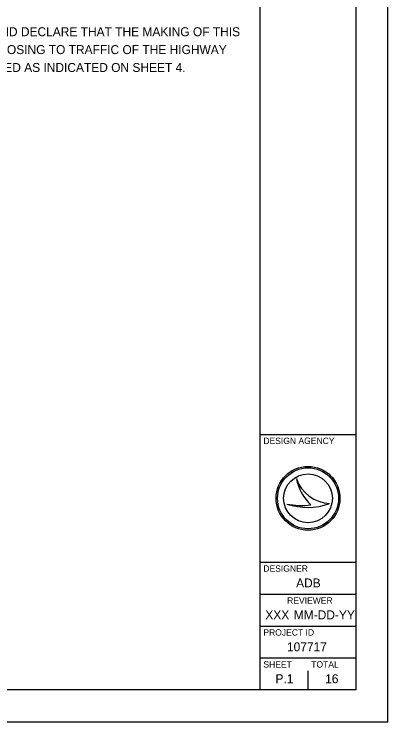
# Model space of a CAD drawing. Extents: x 0 to 34, y 0 to 22.
# Drawn here: x 28.15 to 34, y 0 to 11.08 of the extents above; entities that cross this region are included whole.
import ezdxf

# ---------------------------------------------------------------- set-up
doc = ezdxf.new("R2010")
doc.units = 0
for name, color, linetype in [('SH_Border', 7, 'Continuous'), ('SH_Cut_Line', 7, 'Continuous'), ('SH_Data', 7, 'Continuous')]:
    doc.layers.add(name, color=color, linetype=linetype)

msp = doc.modelspace()

# ---------------------------------------------------------------- linework, layer by layer
at = {"layer": 'SH_Border'}
for p, q in [((32, 0.5), (32, 21.5)), ((32, 4.5), (33.5, 4.5)), ((32, 2.5), (33.5, 2.5)), ((32, 2), (33.5, 2)), ((32, 1.5), (33.5, 1.5)), ((32, 1), (33.5, 1))]:
    msp.add_line(p, q, dxfattribs=at)
msp.add_lwpolyline([(1.5, 21.5), (33.5, 21.5), (33.5, 0.5), (1.5, 0.5)], close=True, dxfattribs=at)
at = {"layer": 'SH_Cut_Line'}
msp.add_lwpolyline([(0, 0), (34, 0), (34, 22), (0, 22)], close=True, dxfattribs=at)
at = {"layer": 'SH_Data'}
for p, q in [((32.567, 3.81), (32.567, 3.81)), ((32.75, 3.5), (32.75, 3.5)), ((32.417, 3.41), (32.417, 3.41)), ((33.087, 3.419), (33.087, 3.419)), ((32.75, 0.5), (32.75, 0.8)), ((32.375, 0.675), (32.375, 0.675))]:
    msp.add_line(p, q, dxfattribs=at)
for radius in [0.5, 0.477, 0.477, 0.382]:
    msp.add_circle((32.75, 3.5), radius, dxfattribs=at)
for centre, radius, start, end in [((33.116, 3.998), 0.58, 198.9257, 198.9319), ((33.347, 3.97), 0.796, 191.6379, 191.6421), ((33.116, 3.998), 0.58, 198.9319, 267.1657), ((33.347, 3.97), 0.796, 191.6421, 226.0947), ((32.739, 4.37), 1.013, 251.4576, 290.0832), ((32.648, 4.654), 1.266, 259.4964, 259.4995), ((32.739, 4.37), 1.013, 251.4527, 251.4576), ((32.648, 4.654), 1.266, 259.4995, 276.6672)]:
    msp.add_arc(centre, radius, start, end, dxfattribs=at)

# ---------------------------------------------------------------- texts
for s, height, p in [(' I HEREBY APPROVE THESE PLANS AND DECLARE THAT THE MAKING OF THIS', 0.14, (24.528, 10.735)), ('IMPROVEMENT WILL REQUIRE THE CLOSING TO TRAFFIC OF THE HIGHWAY', 0.14, (24.528, 10.455)), ('AND THAT DETOURS WILL BE PROVIDED AS INDICATED ON SHEET 4.', 0.14, (24.528, 10.175)), ('DESIGN AGENCY', 0.1, (32.05, 4.35)), ('DESIGNER', 0.1, (32.05, 2.35)), ('ADB', 0.14, (32.563, 2.105)), ('REVIEWER', 0.1, (32.422, 1.85)), ('XXX', 0.14, (32.081, 1.605)), ('MM-DD-YY', 0.14, (32.527, 1.605)), ('PROJECT ID', 0.1, (32.05, 1.35)), ('107717', 0.14, (32.42, 1.105)), ('SHEET', 0.1, (32.05, 0.85)), ('TOTAL', 0.1, (32.8, 0.85)), ('P.1', 0.14, (32.24, 0.605)), ('16', 0.14, (33.018, 0.605))]:
    msp.add_text(s, height=height, dxfattribs=at).set_placement(p)

doc.saveas('drawing.dxf')
